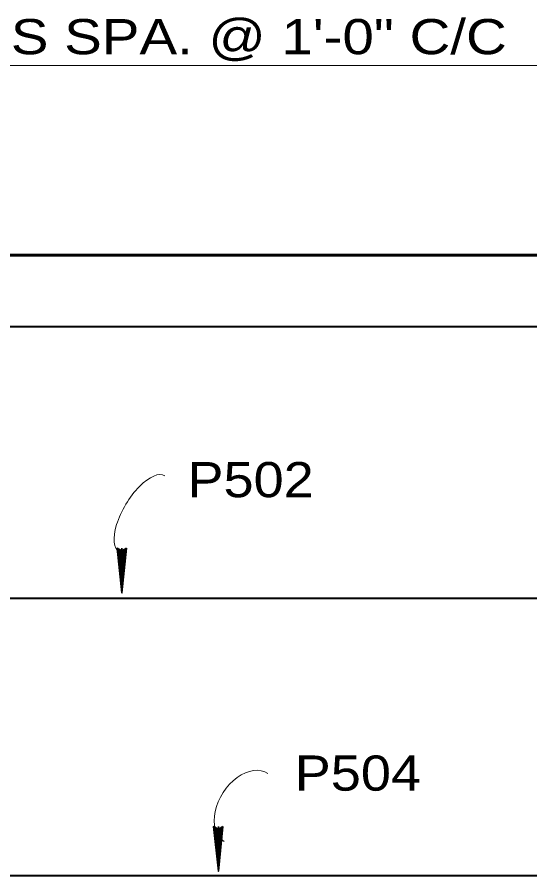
# Model space of a CAD drawing. Extents: x 3.64 to 6.84, y -0.8 to 1.19.
# Drawn here: x 4.2572 to 4.3787, y 0.7218 to 0.9251 of the extents above; entities that cross this region are included whole.
import ezdxf

# ---------------------------------------------------------------- set-up
doc = ezdxf.new("R2010")
doc.units = 0
doc.header["$LTSCALE"] = 0.0033
doc.layers.add('1', color=7, linetype='Continuous', lineweight=40)

msp = doc.modelspace()

# ---------------------------------------------------------------- linework, layer by layer
at = {"layer": '1', "lineweight": 13}
msp.add_line((4.117, 0.913667), (4.533, 0.913667), dxfattribs=at)
at = {"layer": '1', "lineweight": 60}
msp.add_line((4.157167, 0.86875), (4.492917, 0.86875), dxfattribs=at)
at = {"layer": '1', "lineweight": 35}
for p, q in [((4.282083, 0.799333), (4.282083, 0.78875)), ((4.281, 0.799083), (4.281833, 0.79175)), ((4.281167, 0.799083), (4.281917, 0.79175)), ((4.28125, 0.799083), (4.282083, 0.79175)), ((4.281417, 0.799167), (4.282167, 0.791833)), ((4.282917, 0.799083), (4.281917, 0.79125)), ((4.282917, 0.799083), (4.282083, 0.79125)), ((4.283083, 0.799083), (4.282167, 0.79125)), ((4.283083, 0.799083), (4.282167, 0.79125)), ((4.283, 0.799083), (4.282167, 0.79125)), ((4.303833, 0.733167), (4.304667, 0.725833)), ((4.304, 0.733167), (4.30475, 0.725833)), ((4.304083, 0.733167), (4.304917, 0.725833)), ((4.30425, 0.73325), (4.305, 0.725917)), ((4.30575, 0.733167), (4.30475, 0.725333)), ((4.304917, 0.733417), (4.304917, 0.722833)), ((4.30575, 0.733167), (4.304917, 0.725333)), ((4.305917, 0.733167), (4.305, 0.725333)), ((4.305917, 0.733167), (4.305, 0.725333)), ((4.305833, 0.733167), (4.305, 0.725333))]:
    msp.add_line(p, q, dxfattribs=at)
at = {"layer": '1'}
for p, q in [((4.050917, 0.7875), (4.474833, 0.7875)), ((4.39375, 0.72175), (4.171167, 0.72175))]:
    msp.add_line(p, q, dxfattribs=at)
msp.add_lwpolyline([(4.121083, 0.847667), (4.161583, 0.847667), (4.168833, 0.851833), (4.398667, 0.851833)], dxfattribs=at)
at = {"layer": '1', "lineweight": 35}
for points in [[(4.283167, 0.799333), (4.282083, 0.78875), (4.280917, 0.799333), (4.282083, 0.79875)], [(4.282167, 0.798583), (4.28225, 0.793917), (4.282167, 0.793917), (4.282167, 0.794833), (4.28225, 0.798583), (4.282333, 0.795583), (4.282417, 0.79875), (4.2825, 0.7965), (4.282583, 0.79875), (4.282333, 0.79525), (4.282167, 0.790583), (4.281917, 0.7915), (4.281917, 0.79025), (4.281917, 0.798583), (4.28175, 0.796167), (4.28175, 0.79875), (4.282167, 0.793417), (4.2815, 0.79875)], [(4.306, 0.733417), (4.304917, 0.722833), (4.30375, 0.733417), (4.304917, 0.732833)], [(4.305, 0.732667), (4.305083, 0.728), (4.305, 0.728), (4.305, 0.728917), (4.305083, 0.732667), (4.305167, 0.729667), (4.30525, 0.732833), (4.305333, 0.730583), (4.305417, 0.732833), (4.305167, 0.729333), (4.305, 0.724667), (4.30475, 0.725583), (4.30475, 0.724333), (4.30475, 0.732667), (4.304583, 0.73025), (4.304583, 0.732833), (4.305, 0.7275), (4.304333, 0.732833)]]:
    msp.add_lwpolyline(points, close=True, dxfattribs=at)
for points in [[(4.282167, 0.798583), (4.282917, 0.799), (4.282667, 0.79875), (4.282333, 0.798583), (4.282417, 0.798333), (4.28275, 0.7985), (4.282, 0.798667), (4.2815, 0.798833), (4.281083, 0.799083)], [(4.305, 0.732667), (4.30575, 0.733083), (4.3055, 0.732833), (4.305167, 0.732667), (4.30525, 0.732417), (4.305583, 0.732583), (4.304833, 0.73275), (4.304333, 0.732917), (4.303917, 0.733167)]]:
    msp.add_lwpolyline(points, dxfattribs=at)
at = {"layer": '1', "lineweight": 13}
for centre, major_axis, ratio in [((4.286833, 0.807458), (0.005417, 0.009042), 0.424401), ((4.311458, 0.737958), (0.005208, 0.008042), 0.67679)]:
    msp.add_ellipse(centre, major_axis=major_axis, ratio=ratio, start_param=0, end_param=3.1415927, dxfattribs=at)

# ---------------------------------------------------------------- texts
at = {"layer": '1'}
for s, width, p in [('BARS SPA. @ 1\'-0" C/C', 1.2, (4.22825, 0.916333)), ('P502', 1.15, (4.297583, 0.811417)), ('P504', 1.15, (4.323, 0.741917))]:
    msp.add_text(s, height=0.008334, dxfattribs=dict(at, width=width)).set_placement(p)

doc.saveas('drawing.dxf')
